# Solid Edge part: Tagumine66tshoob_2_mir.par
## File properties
Author: KULL
Template: Iso Metric Part.par
Last saved by: KULL
Revision: 2
Application: Solid Edge
Accuracy: 0,990
Username: KULL
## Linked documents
Tagumine66tshoob_2.par
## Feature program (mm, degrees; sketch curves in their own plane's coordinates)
part copy "CopiedPart_1"
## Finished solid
Body 1: solid body, 15 faces, 15 edges, 0 vertices.
  Faces by surface: cylinder 6, plane 6, torus 2, blend 1
  Edges by curve: circle 13, intersection 2
Bounding box of the edges (mm; curved faces can reach further): 20.000 x 45.562 x 11.446, from (-352.46, -85.5617, 50.3651) to (-332.46, -40, 61.811).
Cylindrical faces by radius (mm): R2 x1, R2.5 x1, R2.5057 x1, R3 x2, R5 x1
Toroidal faces (ring radius, tube radius in mm): R4.6 r0.4 x2
Planar faces by outward normal: +x 1, -x 1, oblique 4
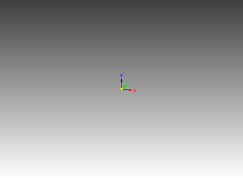
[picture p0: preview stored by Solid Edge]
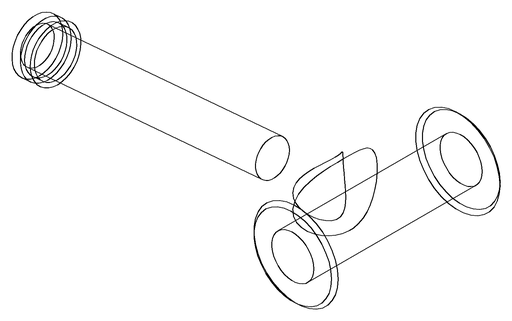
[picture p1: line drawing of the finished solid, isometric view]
